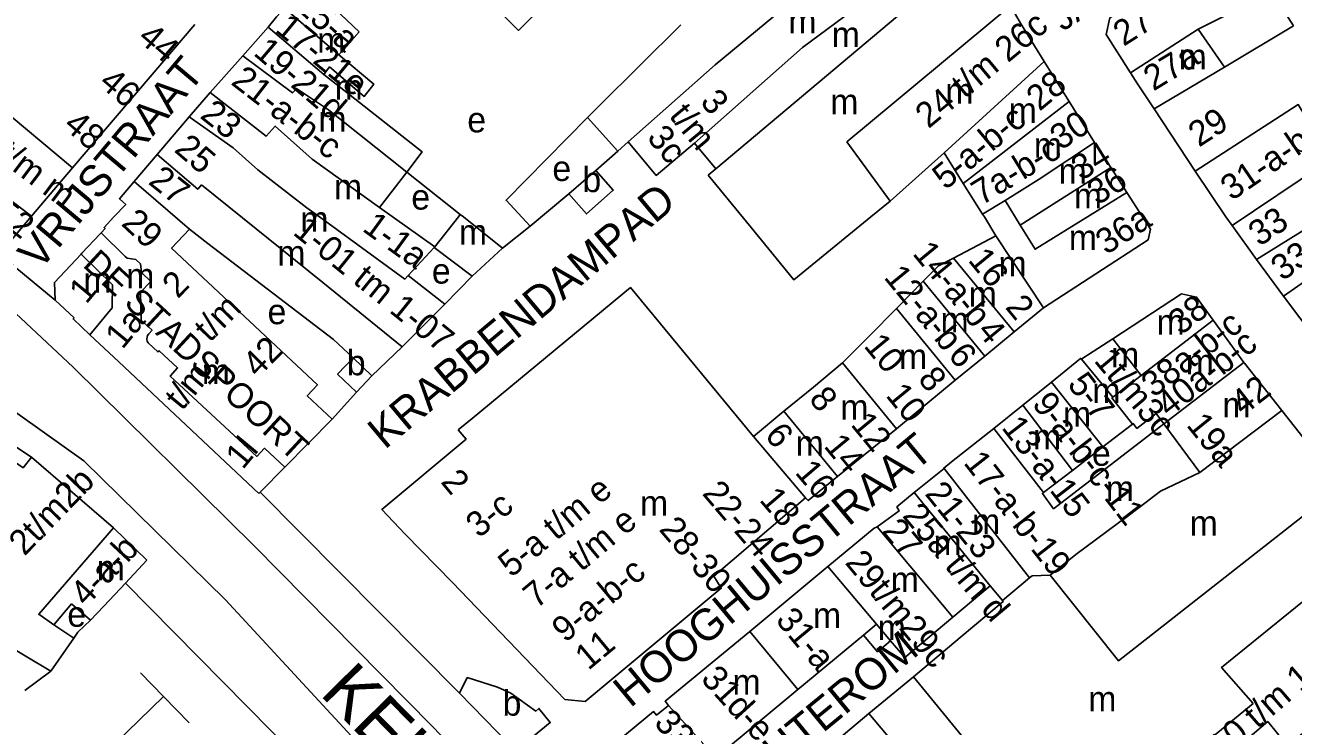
# Model space of a CAD drawing. Extents: x 160673 to 161924, y 382258 to 384145.
# Drawn here: x 161158.4 to 161359.3, y 383169.3 to 383280.3 of the extents above; entities that cross this region are included whole.
import ezdxf

# ---------------------------------------------------------------- set-up
doc = ezdxf.new("R2010")
doc.units = 0
for name, color, linetype in [('BLT_Basislijn', 7, 'Continuous'), ('BLT_Bebouwing', 7, 'Continuous'), ('BLT_Centroide', 7, 'Continuous'), ('BLT_Huisnummer', 7, 'Continuous'), ('BLT_Huisnummer_reeks', 7, 'Continuous'), ('BLT_Onderdoorgang_en_onderverdeling', 7, 'Continuous'), ('BLT_Onderverdeling_panden', 7, 'Continuous'), ('BLT_Straatnaam', 7, 'Continuous'), ('BLT_Straatnaam_hoofdweg', 7, 'Continuous'), ('BLT_Straatnaam_verkleind', 7, 'Continuous')]:
    doc.layers.add(name, color=color, linetype=linetype)

msp = doc.modelspace()

# ---------------------------------------------------------------- linework, layer by layer
at = {"layer": 'BLT_Basislijn'}
for p, q in [((161248.74, 383257.36), (161252.23, 383260.45)), ((161218.81, 383257.11), (161227.29, 383250.39)), ((161244.46, 383253.66), (161238.35, 383248.56)), ((161238.35, 383248.56), (161233.97, 383245.09)), ((161163.13, 383236.85), (161154.26, 383244.11)), ((161224.82, 383236.22), (161229.18, 383240.62)), ((161210.86, 383222.27), (161206.99, 383218.01)), ((161159.38, 383211.99), (161148.97, 383218.79)), ((161195.58, 383206.4), (161227.18, 383174.61)), ((161174.28, 383192.04), (161221.81, 383143.81)), ((161176.63, 383177.82), (161180.3, 383174.05)), ((161163.29, 383157.58), (161180.3, 383174.05)), ((161180.3, 383174.05), (161184.37, 383169.88))]:
    msp.add_line(p, q, dxfattribs=at)
for points in [[(161247.43, 383265.73), (161234.55, 383252.64), (161238.35, 383248.56)], [(161105.33, 383250.78), (161111.05, 383249.36), (161132.16, 383235.51), (161150.93, 383223.25), (161167.67, 383211.41), (161190.11, 383189.36), (161231.21, 383144.85)], [(161151.06, 383240.13), (161165.98, 383226.24), (161194.65, 383197.92), (161222.81, 383169.35), (161244.86, 383146.49), (161270.16, 383120.77), (161279.96, 383109.14)], [(161166.08, 383183.28), (161166.74, 383184.23), (161168.75, 383186.14)], [(161162.43, 383178.08), (161158.35, 383175.04)]]:
    msp.add_lwpolyline(points, dxfattribs=at)
at = {"layer": 'BLT_Bebouwing'}
for p, q in [((161211.3, 383279.3), (161203.15, 383287.07)), ((161185.25, 383280.48), (161165.89, 383257.77)), ((161262.19, 383280.44), (161249.24, 383267.53)), ((161196.88, 383280.04), (161192.85, 383275.52)), ((161208.08, 383275.7), (161211.3, 383279.3)), ((161192.85, 383275.52), (161187.66, 383269.71)), ((161323.69, 383268.3), (161319.73, 383274.65)), ((161208.86, 383270.06), (161205.66, 383272.57)), ((161249.24, 383267.53), (161247.43, 383265.73)), ((161343.69, 383257.28), (161337.15, 383267.12)), ((161184.37, 383265.84), (161179.29, 383259.9)), ((161247.43, 383265.73), (161252.23, 383260.45)), ((161252.23, 383260.45), (161253.9, 383261.91)), ((161264.37, 383261.71), (161267.75, 383257.63)), ((161330.29, 383257.84), (161327.73, 383261.81)), ((161179.29, 383259.9), (161175.65, 383255.62)), ((161295.39, 383252.51), (161303.9, 383260.16)), ((161303.9, 383260.16), (161306.93, 383255.32)), ((161159.38, 383250.12), (161165.89, 383257.77)), ((161214.5, 383251.53), (161218.81, 383257.11)), ((161248.74, 383257.36), (161244.46, 383253.66)), ((161267.75, 383257.63), (161266.55, 383256.64)), ((161273.34, 383248.34), (161266.55, 383256.64)), ((161332.85, 383253.86), (161330.29, 383257.84)), ((161348.51, 383250), (161343.69, 383257.28)), ((161306.93, 383255.32), (161310, 383250.44)), ((161292.32, 383250), (161295.39, 383252.51)), ((161335.33, 383250), (161332.85, 383253.86)), ((161159.27, 383250), (161159.72, 383250.52)), ((161214.5, 383251.53), (161223.24, 383245.28)), ((161227.29, 383250.39), (161226.98, 383250)), ((161227.78, 383250), (161227.29, 383250.39)), ((161310, 383250.44), (161310.28, 383250)), ((161154.26, 383244.11), (161159.38, 383250.12)), ((161223.24, 383245.28), (161226.98, 383250)), ((161233.97, 383245.09), (161227.78, 383250)), ((161310.28, 383250), (161312.12, 383247.01)), ((161348.51, 383250), (161349.5, 383248.64)), ((161349.5, 383248.64), (161353.39, 383243.28)), ((161312.12, 383247.01), (161305.38, 383243.49)), ((161167.24, 383244.12), (161163.04, 383239.62)), ((161219.04, 383240.74), (161223.16, 383245.15)), ((161223.16, 383245.15), (161229.18, 383240.62)), ((161229.18, 383240.62), (161233.97, 383245.09)), ((161353.39, 383243.28), (161357.63, 383237.45)), ((161163.04, 383239.62), (161163.13, 383236.85)), ((161300.61, 383239.82), (161296.36, 383235.5)), ((161296.36, 383235.5), (161292.11, 383231.18)), ((161314.99, 383231.79), (161319.65, 383235.61)), ((161351.39, 383226.97), (161346.54, 383233.68)), ((161173.22, 383227.06), (161168.65, 383231.35)), ((161310.34, 383227.97), (161314.99, 383231.79)), ((161330.61, 383230.71), (161325.9, 383227.63)), ((161218.1, 383229.45), (161213.3, 383224.87)), ((161195.39, 383206.21), (161173.22, 383227.06)), ((161287.84, 383226.9), (161283.2, 383223.06)), ((161305.68, 383224.15), (161310.34, 383227.97)), ((161213.3, 383224.87), (161210.86, 383222.27)), ((161301.03, 383220.33), (161305.68, 383224.15)), ((161283.2, 383223.06), (161278.55, 383219.23)), ((161320.91, 383223.87), (161316.37, 383220.22)), ((161296.35, 383216.48), (161301.03, 383220.33)), ((161316.37, 383220.22), (161311.8, 383216.51)), ((161199.49, 383210.38), (161206.99, 383218.01)), ((161278.55, 383219.23), (161273.73, 383215.23)), ((161366.8, 383207.39), (161357.38, 383219.36)), ((161333.75, 383217.21), (161329.03, 383213.58)), ((161273.73, 383215.23), (161281.98, 383205.54)), ((161159.38, 383211.99), (161172.37, 383200.75)), ((161329.03, 383213.58), (161324.22, 383209.88)), ((161195.58, 383206.4), (161199.49, 383210.38)), ((161303.92, 383210.15), (161299.18, 383206.39)), ((161324.22, 383209.88), (161319.65, 383206.37)), ((161195.39, 383206.21), (161195.58, 383206.4)), ((161172.37, 383200.75), (161177.66, 383195.64)), ((161292.81, 383200.7), (161285.49, 383194.65)), ((161177.66, 383195.64), (161174.28, 383192.04)), ((161285.49, 383194.65), (161273.12, 383184.36)), ((161174.28, 383192.04), (161170.84, 383188.37)), ((161311.18, 383191.61), (161305.28, 383186.65)), ((161313.17, 383189.25), (161311.18, 383191.61)), ((161162.94, 383185.44), (161165.74, 383188.76)), ((161165.74, 383188.76), (161168.75, 383186.14)), ((161170.84, 383188.37), (161168.75, 383186.14)), ((161166.08, 383183.28), (161162.94, 383185.44)), ((161293.21, 383185.54), (161291.13, 383183.79)), ((161295.44, 383182.89), (161293.21, 383185.54)), ((161162.43, 383178.08), (161154.26, 383182.93)), ((161166.08, 383183.28), (161162.43, 383178.08)), ((161291.13, 383183.79), (161280.74, 383175.17)), ((161299.07, 383177.19), (161306.44, 383183.4)), ((161299.07, 383177.19), (161292.01, 383171.36)), ((161280.74, 383175.17), (161267.75, 383164.4)), ((161298.29, 383163.9), (161292.01, 383171.36))]:
    msp.add_line(p, q, dxfattribs=at)
msp.add_lwpolyline([(161238.27, 383295.02), (161245.11, 383288.07), (161236.49, 383279.55), (161229.67, 383286.48)], close=True, dxfattribs=at)
for points in [[(161333.41, 383272.83), (161329.59, 383278.88), (161330.17, 383281.53), (161341.91, 383289.1)], [(161199.45, 383283.06), (161198.18, 383281.69), (161196.88, 383280.04)], [(161319.73, 383274.65), (161315.98, 383280.68), (161314.41, 383283.42)], [(161205.66, 383272.57), (161206.58, 383273.76), (161212.08, 383269.09), (161213.59, 383271.05), (161208.08, 383275.7)], [(161337.15, 383267.12), (161334.51, 383271.09), (161333.41, 383272.83)], [(161187.66, 383269.71), (161184.37, 383265.84)], [(161218.81, 383257.11), (161221.27, 383260.3), (161208.86, 383270.06)], [(161327.73, 383261.81), (161323.69, 383268.3)], [(161253.9, 383261.91), (161258.31, 383256.58), (161264.37, 383261.71)], [(161244.46, 383253.66), (161247.27, 383250.49), (161251.5, 383254.23), (161248.74, 383257.36)], [(161175.65, 383255.62), (161173.32, 383252.89), (161174.3, 383251.97), (161172.45, 383250)], [(161172.45, 383250), (161170.88, 383248.33), (161171.04, 383248.17), (161170.41, 383247.51)], [(161292.32, 383250), (161280.13, 383240.03), (161273.34, 383248.34)], [(161319.65, 383235.61), (161336.2, 383246.37), (161336.57, 383248.09), (161335.33, 383250)], [(161170.41, 383247.51), (161170.28, 383247.36), (161167.38, 383244.28), (161167.24, 383244.12)], [(161206.99, 383218.01), (161203.06, 383221.69), (161204.66, 383223.41), (161181.56, 383245.05), (161184.4, 383248.09)], [(161184.4, 383248.09), (161187.29, 383245.79), (161207.2, 383230.62)], [(161305.38, 383243.49), (161303, 383242.25), (161300.61, 383239.82)], [(161224.82, 383236.22), (161219.04, 383240.74)], [(161273.73, 383215.23), (161254.22, 383238.82), (161229.15, 383218.08), (161226.97, 383216.3)], [(161163.13, 383236.85), (161166.12, 383234.03), (161165.97, 383233.87), (161168.65, 383231.35)], [(161218.1, 383229.45), (161224.82, 383236.22)], [(161346.54, 383233.68), (161343.9, 383237.33), (161341.48, 383237.84), (161330.61, 383230.71)], [(161357.63, 383237.45), (161362.84, 383230.58)], [(161207.2, 383230.62), (161210.3, 383227.7)], [(161292.11, 383231.18), (161287.84, 383226.9)], [(161210.3, 383227.7), (161207.86, 383225.1), (161210.86, 383222.27)], [(161325.64, 383227.46), (161325.53, 383227.61), (161320.91, 383223.87)], [(161325.9, 383227.63), (161325.64, 383227.46)], [(161357.38, 383219.36), (161351.49, 383226.84), (161351.39, 383226.97)], [(161338.72, 383217.23), (161337.47, 383218.86), (161334.44, 383216.53), (161333.85, 383217.29), (161333.75, 383217.21)], [(161226.97, 383216.3), (161228.2, 383214.82), (161214.89, 383203.68), (161218.57, 383199.78), (161226.06, 383192.11), (161243.85, 383173.6), (161247.05, 383173.28), (161268.61, 383191.22), (161267.43, 383193.11), (161281.98, 383205.54)], [(161287.01, 383208.93), (161296.35, 383216.48)], [(161311.8, 383216.51), (161305.06, 383211.22), (161303.86, 383210.23), (161303.92, 383210.15)], [(161319.65, 383206.37), (161319.47, 383206.23), (161321.25, 383203.8), (161338.72, 383217.23)], [(161147.15, 383215.76), (161154.67, 383210.22), (161155.83, 383211.82), (161158.06, 383210.29), (161159.38, 383211.99)], [(161281.98, 383205.54), (161282.38, 383205.08), (161287.01, 383208.93)], [(161299.18, 383206.39), (161296.43, 383204.1), (161296.79, 383203.46), (161293.29, 383200.93)], [(161293.29, 383200.93), (161292.81, 383200.7)], [(161306.44, 383183.4), (161313.26, 383189.13), (161313.17, 383189.25)], [(161305.28, 383186.65), (161297.67, 383180.24), (161295.44, 383182.89)], [(161273.12, 383184.36), (161259.72, 383173.31), (161260.26, 383172.66)], [(161295.44, 383182.89), (161293.36, 383181.14), (161291.13, 383183.79)], [(161227.18, 383174.61), (161228.4, 383177.07), (161233.17, 383175.57), (161235.31, 383174.59), (161239.24, 383171.76), (161239.73, 383172.17), (161241.54, 383169.94), (161237.08, 383166.29)], [(161235.13, 383166.43), (161227.18, 383174.61)], [(161260.26, 383172.66), (161258.38, 383171.11), (161257.91, 383171.68), (161253.59, 383168.16), (161250.48, 383165.6)], [(161292.01, 383171.36), (161270.52, 383153.27), (161268.37, 383155.82), (161268.04, 383156.22)]]:
    msp.add_lwpolyline(points, dxfattribs=at)
at = {"layer": 'BLT_Onderdoorgang_en_onderverdeling'}
msp.add_lwpolyline([(161319.4, 383155.58), (161312.56, 383163.95), (161310.96, 383162.64), (161299.07, 383177.19)], dxfattribs=at)
at = {"layer": 'BLT_Onderverdeling_panden'}
for p, q in [((161267.75, 383257.63), (161309.21, 383292.52)), ((161359.25, 383280.25), (161354.7, 383287.55)), ((161208.08, 383275.7), (161199.45, 383283.06)), ((161288.48, 383261.9), (161314.41, 383283.42)), ((161205.66, 383272.57), (161196.88, 383280.04)), ((161333.41, 383272.83), (161344.16, 383279.72)), ((161348.3, 383273.74), (161344.16, 383279.72)), ((161348.3, 383273.74), (161359.25, 383280.25)), ((161303.9, 383260.16), (161319.73, 383274.65)), ((161147.91, 383272.82), (161165.89, 383257.77)), ((161337.15, 383267.12), (161348.3, 383273.74)), ((161306.93, 383255.32), (161323.69, 383268.3)), ((161218.81, 383257.11), (161206.4, 383266.95)), ((161370.9, 383263.04), (161349.5, 383248.64)), ((161288.48, 383261.9), (161295.39, 383252.51)), ((161318.97, 383255.97), (161327.73, 383261.81)), ((161147.71, 383258.97), (161159.38, 383250.12)), ((161315.95, 383248.73), (161330.29, 383257.84)), ((161374.73, 383256.53), (161353.39, 383243.28)), ((161313.55, 383252.63), (161318.97, 383255.97)), ((161310, 383250.44), (161313.55, 383252.63)), ((161315.95, 383248.73), (161313.55, 383252.63)), ((161312.12, 383247.01), (161319.65, 383235.61)), ((161223.16, 383245.15), (161223.24, 383245.28)), ((161305.38, 383243.49), (161314.99, 383231.79)), ((161300.61, 383239.82), (161310.34, 383227.97)), ((161296.36, 383235.5), (161305.68, 383224.15)), ((161335.09, 383224.88), (161346.54, 383233.68)), ((161335.09, 383224.88), (161330.61, 383230.71)), ((161210.3, 383227.7), (161213.3, 383224.87)), ((161287.84, 383226.9), (161296.35, 383216.48)), ((161330.65, 383221.46), (161325.64, 383227.46)), ((161338.72, 383217.23), (161351.39, 383226.97)), ((161330.65, 383221.46), (161335.09, 383224.88)), ((161329.03, 383213.58), (161320.91, 383223.87)), ((161324.22, 383209.88), (161316.37, 383220.22)), ((161278.55, 383219.23), (161287.01, 383208.93)), ((161357.38, 383219.36), (161344.38, 383209.54)), ((161319.65, 383206.37), (161311.8, 383216.51)), ((161338.72, 383217.23), (161344.38, 383209.54)), ((161303.92, 383210.15), (161317.45, 383192.86)), ((161311.18, 383191.61), (161299.18, 383206.39)), ((161305.28, 383186.65), (161293.29, 383200.93)), ((161293.21, 383185.54), (161285.49, 383194.65)), ((161313.17, 383189.25), (161317.45, 383192.86)), ((161280.74, 383175.17), (161273.12, 383184.36)), ((161267.75, 383164.4), (161260.26, 383172.66)), ((161330.3, 383154.53), (161352.86, 383172.98)), ((161346.84, 383163.07), (161355.17, 383170.11))]:
    msp.add_line(p, q, dxfattribs=at)
for points in [[(161253.9, 383261.91), (161267.64, 383274.12), (161284.7, 383288.24), (161304.05, 383301.55)], [(161264.37, 383261.71), (161281.46, 383276.83), (161290.62, 383283.62), (161290.48, 383283.98), (161307.12, 383296.18)], [(161344.16, 383279.72), (161348.13, 383281.75), (161347.43, 383282.95)], [(161206.4, 383266.95), (161201.37, 383270.35), (161200.71, 383269.65), (161192.85, 383275.52)], [(161214.5, 383251.53), (161203.83, 383259.17), (161197.98, 383264.39), (161196.54, 383262.79), (161187.66, 383269.71)], [(161343.69, 383257.28), (161359.99, 383267.81), (161361.92, 383264.62), (161367.53, 383268.57), (161370.9, 383263.04)], [(161219.04, 383240.74), (161218.51, 383240.18), (161205, 383250), (161203, 383251.45), (161195.21, 383257.47), (161191.31, 383260.93), (161184.37, 383265.84)], [(161186.32, 383255.08), (161185.71, 383254.39), (161179.29, 383259.9)], [(161357.63, 383237.45), (161373.03, 383248.17), (161389.41, 383257.99)], [(161184.4, 383248.09), (161175.65, 383255.62)], [(161218.1, 383229.45), (161205.5, 383239.62), (161186.32, 383255.08)], [(161332.85, 383253.86), (161318.31, 383244.9), (161315.95, 383248.73)], [(161170.41, 383247.51), (161174.24, 383243.74), (161174.53, 383243.47), (161175.89, 383243.25), (161176.65, 383242.57), (161176.81, 383241.23), (161178.3, 383239.76), (161176.64, 383238.07), (161176.76, 383233.65), (161178.48, 383232.06), (161177.95, 383231.49)], [(161168.65, 383231.35), (161172.18, 383235.6), (161172.19, 383239.28), (161167.24, 383244.12)], [(161177.95, 383231.49), (161177.78, 383231.24), (161177.68, 383230.95), (161177.67, 383230.65), (161177.73, 383230.36), (161177.87, 383230.09), (161177.93, 383230)], [(161177.93, 383230), (161179.41, 383228.63), (161179.59, 383228.83), (161182.53, 383226.1), (161181.34, 383224.82), (161195.08, 383212.09), (161196.27, 383213.37), (161199.49, 383210.38)], [(161333.75, 383217.21), (161330.48, 383221.34), (161330.65, 383221.46)], [(161320.71, 383193.3), (161324.78, 383196.53), (161334.78, 383204.01), (161338.19, 383206.56), (161344.38, 383209.54)], [(161320.71, 383193.3), (161331.53, 383179.7), (161366.8, 383207.39)], [(161162.94, 383185.44), (161160.54, 383187.1), (161172.37, 383200.75)], [(161373.21, 383199.25), (161347.85, 383178.66), (161352.86, 383172.98)], [(161317.45, 383192.86), (161317.86, 383193.2), (161320.71, 383193.3)], [(161355.17, 383170.11), (161358.25, 383166.29), (161372.09, 383177.09), (161384.18, 383187.52)]]:
    msp.add_lwpolyline(points, dxfattribs=at)

# ---------------------------------------------------------------- texts
at = {"layer": 'BLT_Centroide'}
for s, p in [('m', (161279.24, 383279.06)), ('m', (161204.63, 383276.03)), ('m', (161286.11, 383276.91)), ('m', (161341.04, 383273.41)), ('m', (161207.38, 383268.56)), ('m', (161304.1, 383267.97)), ('m', (161285.88, 383266.28)), ('m', (161204.82, 383263.53)), ('e', (161228.4, 383263.4)), ('m', (161314.13, 383264.91)), ('m', (161318.12, 383259.38)), ('e', (161241.87, 383255.7)), ('m', (161322.04, 383255.28)), ('b', (161246.63, 383253.94)), ('m', (161207.28, 383252.78)), ('e', (161219.53, 383251.17)), ('m', (161324.46, 383251.38)), ('m', (161201.96, 383247.66)), ('m', (161227.07, 383245.62)), ('m', (161323.66, 383244.75)), ('m', (161198.31, 383242.31)), ('e', (161222.79, 383239.45)), ('m', (161312.52, 383240.61)), ('m', (161167.61, 383238.03)), ('m', (161174.39, 383238.68)), ('m', (161307.8, 383235.81)), ('e', (161196.77, 383233.02)), ('m', (161303.34, 383231.73)), ('m', (161337.55, 383231.38)), ('b', (161209.32, 383224.94)), ('m', (161296.77, 383225.91)), ('m', (161330.36, 383226.17)), ('m', (161342.18, 383225.09)), ('m', (161186.36, 383223.53)), ('m', (161327.38, 383220.52)), ('m', (161287.47, 383217.89)), ('m', (161347.99, 383218.25)), ('m', (161322.73, 383216.81)), ('m', (161318, 383213.19)), ('m', (161280.39, 383212.19)), ('e', (161327.32, 383210.6)), ('m', (161329.52, 383205.03)), ('m', (161255.75, 383202.71)), ('m', (161308.33, 383199.81)), ('m', (161342.79, 383199.53)), ('m', (161302.23, 383196.45)), ('m', (161169.73, 383192.45)), ('m', (161295.45, 383190.61)), ('e', (161165.06, 383185.11)), ('m', (161283.14, 383184.94)), ('m', (161293.39, 383183.02)), ('m', (161270.4, 383174.38)), ('b', (161233.99, 383171.03)), ('m', (161326.73, 383171.7))]:
    msp.add_text(s, height=4, dxfattribs=at).set_placement(p)
at = {"layer": 'BLT_Huisnummer'}
for s, rotation, p in [('27', 32.336, (161332.33, 383276.94)), ('27a', 31.0669, (161337.05, 383269.86)), ('23', 321.5235, (161185.9, 383265.81)), ('34', 31.6438, (161325.63, 383255.65)), ('27', 321.5216, (161177.71, 383255.35)), ('36', 31.6427, (161328.17, 383251.77)), ('36a', 33.0091, (161329.59, 383243.92)), ('33a', 34.8369, (161357.46, 383239.76)), ('38', 37.5576, (161341.38, 383231.17))]:
    msp.add_text(s, height=4, rotation=rotation, dxfattribs=at).set_placement(p)
at = {"layer": 'BLT_Huisnummer_reeks'}
for s, rotation, p in [('15-a', 318.1325, (161201.03, 383283.08)), ('17-21e', 320.3764, (161197.79, 383279.47)), ('24 t/m 26c', 39.6797, (161301.44, 383263.9)), ('44', 319.5677, (161176.03, 383278.05)), ('19-21d', 319.589, (161194.37, 383275.77)), ('46', 319.5677, (161169.88, 383270.95)), ('21-a-b-c', 322.3772, (161190.8, 383271.12)), ('28', 39.6186, (161319.02, 383266.65)), ('50-a t/m m', 322.8587, (161144.07, 383266.63)), ('3', 309.5945, (161265.14, 383268.17)), ('t/m', 309.5945, (161260.22, 383265.96)), ('5-a-b-c', 39.6186, (161304.14, 383254.17)), ('30', 33.7142, (161322.4, 383260.47)), ('29', 32.8624, (161344.26, 383260.97)), ('48', 319.5677, (161164.26, 383264.2)), ('3c', 309.5945, (161256.7, 383262.5)), ('31-a-b-c', 34.4279, (161349.46, 383252.47)), ('25', 319.3884, (161181.82, 383260.46)), ('7a-b-c', 31.6382, (161309.83, 383251.75)), ('52', 323.1137, (161153.1, 383249.92)), ('29', 316.8689, (161173.46, 383248.8)), ('1-1a', 323.9964, (161211.6, 383247.91)), ('33', 33.9403, (161353.83, 383245.23)), ('1-01 tm 1-07', 321.1175, (161200.61, 383247.34)), ('14-a-b', 309.3941, (161298.78, 383244.16)), ('16', 309.3962, (161307.57, 383243.12)), ('12-a-b', 309.3951, (161294.24, 383240.4)), ('2', 45.5076, (161182.55, 383236.96)), ('1', 50.2436, (161168.06, 383236.08)), ('t/m', 45.5076, (161187.61, 383230.01)), ('2', 309.3962, (161313.46, 383235.67)), ('1a', 50.2436, (161173.78, 383228.91)), ('38a-b-c', 37.5582, (161337.1, 383221.29)), ('4', 309.3941, (161308.98, 383231.86)), ('42', 45.5076, (161195.25, 383224.42)), ('10', 309.3967, (161291.06, 383229.54)), ('40a-b-c', 38.1268, (161339.52, 383218.18)), ('6', 309.3951, (161304.39, 383228.06)), ('1t/m3c', 309.8638, (161327.51, 383227.2)), ('t/m', 50.2436, (161183.22, 383219.18)), ('8', 309.3967, (161299.62, 383224.27)), ('5-7', 307.5571, (161323.31, 383223.47)), ('42', 38.1268, (161351.29, 383218.41)), ('8', 309.3949, (161282.36, 383221.11)), ('10', 309.3967, (161294.53, 383221.7)), ('9-a-b-c-11', 307.5554, (161317.71, 383220.37)), ('12', 309.3949, (161288.99, 383217.09)), ('13-a-15', 307.5561, (161312.89, 383216.62)), ('19a', 309.0647, (161342.15, 383217)), ('6', 309.3949, (161275.36, 383215.37)), ('1l', 50.2436, (161192.84, 383209.87)), ('14', 309.3949, (161284.73, 383213.67)), ('17-a-b-19', 308.0462, (161306.86, 383211.04)), ('16', 310.4308, (161280.16, 383209.47)), ('2t/m2b', 45.9857, (161158.27, 383196.19)), ('2', 309.5945, (161224.07, 383208.01)), ('5-a t/m e', 39.594, (161235.37, 383192.79)), ('22-24', 310.4308, (161265.47, 383206.16)), ('21-23', 309.0647, (161300.73, 383206.12)), ('18', 310.4308, (161274.52, 383205.14)), ('3-c', 39.594, (161230.26, 383199.04)), ('25a t/m d', 310.0835, (161297.17, 383202.63)), ('7-a t/m e', 39.728, (161239.35, 383187.85)), ('28-30', 310.4308, (161258.62, 383200.47)), ('27', 310.0086, (161293.89, 383200.21)), ('4-a-b', 46.8408, (161168.06, 383188.16)), ('29t/m29c', 309.6617, (161288.09, 383195.21)), ('9-a-b-c', 39.728, (161243.9, 383182.47)), ('31-a', 309.6649, (161277.08, 383186.1)), ('11', 39.728, (161247.56, 383178.1)), ('10 t/m 16', 40.7885, (161347.9, 383163.98)), ('31d-e', 312.2454, (161265.23, 383176.74)), ('33', 312.2454, (161257.81, 383169.77))]:
    msp.add_text(s, height=4, rotation=rotation, dxfattribs=at).set_placement(p)
at = {"layer": 'BLT_Straatnaam'}
for s, rotation, p in [('VRIJSTRAAT', 49.9696, (161160.68, 383241.37)), ('KRABBENDAMPAD', 39.9107, (161215.33, 383213.08)), ('HOOGHUISSTRAAT', 39.728, (161254.21, 383172.16)), ('ACHTEROM', 39.3719, (161270.64, 383156.67))]:
    msp.add_text(s, height=5, rotation=rotation, dxfattribs=at).set_placement(p)
at = {"layer": 'BLT_Straatnaam_hoofdweg'}
msp.add_text('KEIZERSGRACHT', height=8, rotation=314.6195, dxfattribs=at).set_placement((161204.86, 383174.43))
at = {"layer": 'BLT_Straatnaam_verkleind'}
for s, rotation, p in [('JAN VAN HOOFFSTRAAT', 32.1803, (161322.68, 383279.33)), ('DE STADSPOORT', 317.1765, (161167.34, 383242.25))]:
    msp.add_text(s, height=4, rotation=rotation, dxfattribs=at).set_placement(p)

doc.saveas('drawing.dxf')
